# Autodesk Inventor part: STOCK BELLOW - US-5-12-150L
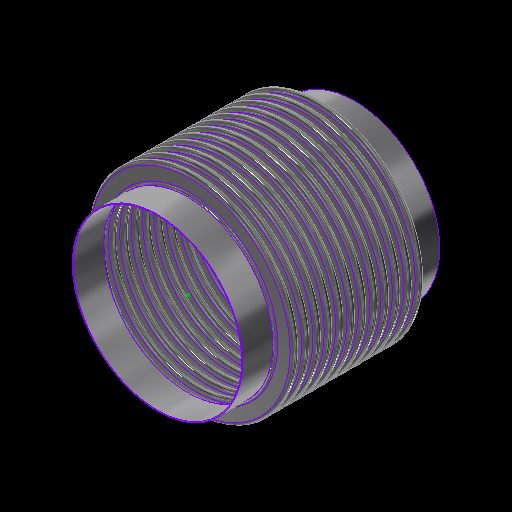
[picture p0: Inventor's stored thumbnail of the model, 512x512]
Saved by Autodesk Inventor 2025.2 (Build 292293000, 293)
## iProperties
Category: 22 GA (0.030 THICK)
RuleStatus: InUse
Created: 2024-01
Part Number: STOCK BELLOW - US-5-12-150L
Project: =STOCK BELLOWS: <Stock Number><SFILL>
Material: ASTM A240-304
Description: =STOCK BELLOWS: <Stock Number>, <SID_> I.D., <SOD_> O.D., <SPLY_> PLY, <Category>, <SNET_CONS> CONS.<PITCH_><STANGENT_> TANGENT<SFILL>
Document SubType Name: Sheet Metal
Designer: GS
Stock Number: U.S-5-12-150L
Surface Area: 4700.15 cm^2
Volume: 178.298 cm^3
Sheet Metal Rule: Default
Appearance: STAINLESS STEEL
Mass: 1436.6 g
Density: 8.05729 g/cm^3
THK: 0.036
ID: 3.500
OD: 4.250
CONS_: 2
PITCH: 0.500
TANGENT: 0.500
BELLOWS_UPSET: 0.000
d79: 1.000
d82: 1.000
d83: 26.000
d84: 24.000
d174: 8
d214: 8
STHK_: 0.030
SID_: 5.563
SOD_: 6.813
SPITCH_: 0.375
STANGENT__: 1.000
SBELLOWS_UPSET_: 0.000
SDIFF_TAN: 1.000
d252: 2
d275: 2
d287: 0.050
d289: 0.500
d290: 0.000
SOD_NECK: 5 5/8
PLY: 1
PSET: 4.178
PBAR: 1.035
COUNTER: 1.500
NET_TUBE: 3.071
CONS: 2
S_CONS: 0
NET_CONS: 2
ID_M: 88.90 mm
OD_M: 107.95 mm
THK_M: 0.91 mm
ID_U: 3.500 in
OD_U: 4.250 in
THK_U: 0.036 in
TANGENT2: 0.500
TAN_TO_TAN: 1.000 in
d80: 2.571
d81: 10
SID: 2.375
SCONS_: 12
SPITCH: 0.250
STANGENT_: 1.000
SBELLOWS_UPSET: 0.000
SNET_CONS: 12
SS_CONS: 0
SCONS: 8
d190: 8
d191: 1
d192: 1
d193: 8
d194: 0
SIZE: 5.00
PRESSURE: 150
d230: 8
STANGENT: 4.000
SPLY_: 1
d233: 8
d234: 0
d263: 2
d265: 1
d268: 2
d269: 0
d286: 2
d288: 1
d291: 2
d292: 0
SREROLL: 0.750
BLETP: 1.000 ul
PRES_Copy: 85
MATTABLE: 20 GA (0.036 THICK)
PART_NUMBER: U.S-5-12-150L
PITCH_: =, <SPITCH_> PITCH,
CFILL: .
SFILL: .
MESH: ,
COMP: 1.03
EXT: 0.52
LAT: 0.25
ANG: 573
ASR: 1021
LSR: 2605
ANSR: 77
PRES: 150
COMPM: 10.3
EXTM: 5.15
LATM: 2.50
ASRM: 178.808
PRESM: 10.342
LSRM: 456.214
ANSRM: 13.485
TEMPMIN: 20
TEMPMAX: 800
TEMPMINM: -7
TEMPMAXM: 427
WEIGHTM: 1.437
WEIGHT: 3.167
Author: GS
Keywords: 20 GA (0.036 THICK)
Comments: =STOCK BELLOW - <STOCK NUMBER>
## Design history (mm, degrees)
sketch "Sketch2"
  geometry: L1 (0, -177.245)-(0, 562.856) reference; L2 (45.364, 0)-(44.45, 0); L3 (48.082, -2.718)-(50.343, -2.718); L4 (48.082, -3.632)-(50.343, -3.632); L5 (50.343, -9.982)-(48.082, -9.982); L6 (50.343, -9.068)-(48.082, -9.068); L7 (45.364, -12.7)-(44.45, -12.7); L8 (48.082, 0)-(48.082, -12.7); L9 (50.343, -6.35)-(53.975, -6.35); L10 (44.45, 0)-(44.45, -12.7); L11 (20.376, 102.841)-(20.376, 101.926); L12 (58.262, 457.127)-(58.262, 349.177); L13 (58.262, 444.427)-(58.262, 336.477); L14 (93.133, -58.817)-(93.133, -71.517); L15 (118.746, -66.401)-(118.746, -66.401); L16 (50.343, -9.068)-(50.343, -9.982); L17 (48.082, -9.068)-(48.082, -9.982); L18 (48.082, -9.525)-(50.343, -9.525); L19 (53.975, 0)-(53.975, -12.7); L20 (-50.343, -9.068)-(-50.343, -9.982); L21 (-50.343, -2.718)-(-48.082, -2.718); L22 (-50.343, -3.632)-(-48.082, -3.632); L23 (-48.082, -9.068)-(-50.343, -9.068); L24 (-50.343, -9.525)-(-48.082, -9.525); L25 (-48.082, -9.982)-(-50.343, -9.982); L26 (-48.082, -9.068)-(-48.082, -9.982); L27 (-44.45, 0.653)-(-44.45, -12.047); L28 (-48.082, -6.35)-(-44.45, -6.35); L29 (-50.343, 0.653)-(-50.343, -12.7); L30 (-53.061, 0)-(-53.975, 0); L31 (-53.975, 0)-(-53.975, -12.7); L32 (-53.061, -12.7)-(-53.975, -12.7); A1 r 2.718 centre (48.082, 0) between (45.364, 0) and (48.082, -2.718); A2 r 3.632 centre (48.082, 0) between (44.45, 0) and (48.082, -3.632); A3 r 3.632 centre (50.343, -6.35) between (50.343, -9.982) and (50.343, -2.718); A4 r 2.718 centre (50.343, -6.35) between (50.343, -9.068) and (50.343, -3.632); A5 r 2.718 centre (48.082, -12.7) between (48.082, -9.982) and (45.364, -12.7); A6 r 3.632 centre (48.082, -12.7) between (48.082, -9.068) and (44.45, -12.7); A7 r 3.175 centre (50.343, -6.35) between (50.343, -9.525) and (53.518, -6.35); A8 r 3.175 centre (48.082, -12.7) between (48.082, -9.525) and (44.907, -12.7); A9 r 2.718 centre (-50.343, -12.7) between (-50.343, -9.982) and (-53.061, -12.7); A10 r 2.718 centre (-48.082, -6.35) between (-48.082, -9.068) and (-48.082, -3.632); A11 r 3.175 centre (-48.082, -6.35) between (-48.082, -9.525) and (-44.907, -6.35); A12 r 3.632 centre (-48.082, -6.35) between (-48.082, -9.982) and (-48.082, -2.718); A13 r 3.175 centre (-50.343, -12.7) between (-50.343, -9.525) and (-53.518, -12.7); A14 r 3.632 centre (-50.343, -12.7) between (-50.343, -9.068) and (-53.975, -12.7); A15 r 2.718 centre (-50.343, 0) between (-53.061, 0) and (-50.343, -2.718); A16 r 3.632 centre (-50.343, 0) between (-53.975, 0) and (-50.343, -3.632); 10 further points
  constraints: 62 end point, 38 point on circle, 20 tangent, 16 centre point, 12 parallel, 9 midpoint, 7 vertical, 6 coincident, 6 concentric, 6 point on line, 4 equal radius, 4 perpendicular, 3 horizontal, 1 collinear, 1 horizontal alignment, 10 other
  dimensions: "THK" = 0.9144 distance of L11.start L11.end; "ID" = 88.9 distance of L11.end point (20.376, 13.026); "OD" = 107.95 distance of L12.start L12.end; "PITCH" = 12.7 distance of L12.start L13.start; "TANGENT" = 12.7 distance of L14.start L14.end; "BELLOWS_UPSET" = 0 distance of L15.start L15.end; "d43" = 88.9 diameter of L10 L1 (= ID); "d44" = 107.95 diameter of L9.end L1 (= OD); "d45" = 0.9144 distance between parallel lines of L5 L6 (computed from THK, PLY); "d46" = 3.6322 radius of A3 (computed from PITCH, THK, PLY); "UPSET_PITCH" = 12.7 distance of L2.end L7.end (derived); "SIDEWALL_ANGLE" = 360 deg dimension on L3 L9 (derived); "CON_GAP" = 5.4356 distance of point (48.082, -9.068) point (48.082, -3.632) (derived); "TAN1" = 4.98728 dimension on A8 (derived); "TAN2" = 4.98728 dimension on A7 (derived); "LEG1" = 2.2606 distance of L18.start L18.end (derived); "d278" = 0.9144 distance between parallel lines of L25 L23 (derived); "d279" = 3.6322 radius of A12 (derived); "d280" = 12.7 distance of L30.end L31.end (derived); "d281" = 360 deg dimension on L21 L28 (derived); "d282" = 5.4356 distance of point (-50.343, -9.068) point (-50.343, -3.632) (derived); "d283" = 4.98728 dimension on A13 (derived); "d284" = 4.98728 dimension on A11 (derived); "d285" = 2.2606 distance of L24.start L24.end (derived); "d293" = 88.9 diameter of L27 L1 (derived); "d294" = 107.95 diameter of L31 L1 (derived)
  node "Sketch Rectangular Pattern1" dims "d31" = 25.4, "ID" = 88.9
  node "Sketch Rectangular Pattern2" dims "d39" = 25.4, "PITCH" = 12.7
revolve "CONS" stored, may be unused: angle "d48" = 90 deg
node "BELLOW MIDPLANE"
pattern_linear "Rectangular Pattern2" dims "d52" = 12.7 (= UPSET_PITCH)
sketch "Sketch5"
  geometry: C1 r 45.364 at (0, 0) reference; C2 r 44.45 at (0, 0) reference
extrude "TANGENT" new body sketch "Sketch5" distance "d53" = 12.7 (= TANGENT); taper "d54" = 0 deg
revolve "SAMETAN" stored, may be unused: angle "d65" = 90 deg
revolve "DIFFTAN" stored, may be unused: angle "d70" = 90 deg
sketch "Sketch9"
  geometry: L1 (53.319, 0)-(-53.319, 0) reference; L2 (0, -17.78)-(0, 17.78) reference; L3 (38.085, 0)-(-38.085, 0); L4 (38.085, -11.906)-(38.085, 11.906); L5 (25.385, -11.906)-(25.385, 11.906); L6 (13.15, 11.906)-(13.15, -11.906); L7 (-25.385, -11.906)-(-25.385, 11.906); L8 (-38.085, -11.906)-(-38.085, 11.906); L9 (37.291, -11.906)-(37.291, 11.906); L10 (38.085, -11.906)-(37.291, -11.906); L11 (38.085, 11.906)-(37.291, 11.906); L12 (13.546, 11.906)-(12.753, 11.906); L13 (12.753, 11.906)-(12.753, -11.906); L14 (12.753, -11.906)-(13.546, -11.906); L15 (13.546, -11.906)-(13.546, 11.906); L16 (-13.546, 11.906)-(-13.546, -11.906); L17 (-13.15, 11.906)-(-13.15, -11.906); L18 (-13.546, -11.906)-(-12.753, -11.906); L19 (-12.753, -11.906)-(-12.753, 11.906); L20 (-12.753, 11.906)-(-13.546, 11.906); L21 (-38.085, -11.906)-(-37.291, -11.906); L22 (-37.291, -11.906)-(-37.291, 11.906); L23 (-37.291, 11.906)-(-38.085, 11.906); L24 (-38.085, 11.906)-(-38.085, -11.906); L25 (38.085, -0.397)-(-38.085, -0.397); L26 (-38.085, -0.397)-(-38.085, 0.397); L27 (-38.085, 0.397)-(38.085, 0.397); L28 (38.085, 0.397)-(38.085, -0.397); L29 (-38.085, 11.906)-(38.085, 11.906); L30 (38.085, 11.906)-(38.085, 12.7); L31 (38.085, 12.7)-(-38.085, 12.7); L32 (-38.085, 12.7)-(-38.085, 11.906); L33 (38.085, -11.906)-(-38.085, -11.906); L34 (-38.085, -11.906)-(-38.085, -12.7); L35 (-38.085, -12.7)-(38.085, -12.7); L36 (38.085, -12.7)-(38.085, -11.906); 30 further points
  constraints: 68 end point, 13 midpoint, 13 parallel, 8 horizontal, 7 perpendicular, 6 equal length, 3 point on line, 2 vertical, 14 other
  dimensions: "d115" = 23.8125 distance of L4.start L4.end (derived); "d116" = 12.7 distance between parallel lines of L4 L5 (derived); "d117" = 12.23516 distance between parallel lines of L5 L6 (derived); "d125" = 38.53427 distance between parallel lines of L7 L6 (derived); "d127" = 12.7 distance between parallel lines of L8 L7 (derived); "d128" = 24.93516 distance between parallel lines of L6 L4 (derived); "d130" = 76.16943 distance between parallel lines of L8 L4 (derived); "RULER_THK" = 0.79375 distance between parallel lines of L4 L9; "d135" = 0.79375 distance of L13.end L14.end (derived); "d138" = 26.29911 distance of L13.end L16.end (derived); "d143" = 0.79375 distance of L22.end L8.end (derived); "d144" = 0.79375 distance between parallel lines of L27 L25 (derived)
extrude "RULER" join sketch "Sketch9" distance "d149" = 0.79375 (derived); taper "d150" = 0 deg
extrude "BARS" join sketch "Sketch9" distance "d151" = 0.79375 (derived); taper "d152" = 0 deg
pattern_linear "Rectangular Pattern4" dims "d155" = 26.29911 (derived)
sketch "Sketch13"
  geometry: L1 (93.149, -52.467)-(93.149, -77.867); L2 (71.412, 0)-(70.65, 0); L3 (71.412, -9.525)-(70.65, -9.525); L4 (83.763, -7.525)-(73.412, -7.525); L5 (83.763, -6.763)-(73.412, -6.763); L6 (83.763, -4.763)-(86.525, -4.763); L7 (73.412, -2)-(83.763, -2); L8 (73.412, 0)-(73.412, -9.525); L9 (70.65, 0)-(70.65, -9.525); L10 (58.254, -323.381)-(58.254, -496.431); L11 (58.254, -332.906)-(58.254, -505.956); L12 (58.254, -351.956)-(58.254, -525.006); L13 (58.254, -361.481)-(58.254, -534.531); L14 (58.254, -371.006)-(58.254, -544.056); L15 (58.254, -380.531)-(58.254, -553.581); L16 (58.254, -390.056)-(58.254, -563.106); L17 (58.254, -342.431)-(58.254, -515.481); L18 (20.376, 102.688)-(20.376, 101.926); L19 (73.412, -2.762)-(83.763, -2.762); L20 (0, -696.265)-(0, 235.847) reference; L21 (-23.752, 0)-(142.514, 0) reference; A1 r 2 centre (73.412, 0) between (71.412, 0) and (73.412, -2); A2 r 2 centre (73.412, -9.525) between (73.412, -7.525) and (71.412, -9.525); A3 r 2.762 centre (73.412, -9.525) between (73.412, -6.763) and (70.65, -9.525); A4 r 2 centre (83.763, -4.763) between (83.763, -6.763) and (83.763, -2.762); A5 r 2.762 centre (83.763, -4.763) between (83.763, -7.525) and (83.763, -2); A6 r 2.762 centre (73.412, 0) between (70.65, 0) and (73.412, -2.762); 6 further points; 1 other entity
  constraints: 38 end point, 15 point on circle, 9 tangent, 6 centre point, 6 parallel, 5 vertical alignment, 4 point on line, 4 vertical, 3 coincident, 3 concentric, 2 collinear, 2 equal radius, 1 horizontal, 1 perpendicular, 23 other
  dimensions: "SBELLOWS_UPSET_" = 0 distance of point (118.762, -66.401) point (118.762, -66.401); "STOTAL_THK_BELLOW__" = 0.762 distance between parallel lines of L4 L5 (derived); "d224" = 2.76225 radius of A5 (derived); "d225" = 9.525 distance of L2.end L3.end (derived); "SSIDEWALL_ANGLE_" = 360 deg dimension on L7 L6 (derived); "SSCON_GAP_" = 4.0005 distance of point (73.412, -6.763) point (73.412, -2.762) (derived); "d235" = 141.3002 diameter of L9 L20 (derived); "d236" = 173.0502 diameter of L6.end L20 (derived)
  node "Sketch Rectangular Pattern4" dims "d228" = 25.4
  node "Sketch Rectangular Pattern5" dims "d229" = 25.4
revolve "SBELLOW" stored, may be unused: angle "d197" = 90 deg
pattern_linear "Rectangular Pattern5" dims "d204" = 9.525 (derived)
revolve "STANGENT" stored, may be unused: angle "d240" = 90 deg
revolve "SSAMETAN" stored, may be unused: angle "d241" = 90 deg
revolve "SDIFFTAN" stored, may be unused: angle "d246" = 90 deg
revolve "INVCON" stored, may be unused: angle "d295" = 90 deg
pattern_linear "Rectangular Pattern6" dims "d298" = 12.7 (derived)
revolve "INVTANGENT" stored, may be unused: angle "d302" = 90 deg
revolve "INVSAMETAN" stored, may be unused: angle "d307" = 90 deg
revolve "INVDIFFTAN" stored, may be unused: angle "d312" = 90 deg
sketch "ID BELLOW MOUNT CALC"
  geometry: L1 (44.45, 0)-(38.1, 0); L2 (38.1, 0)-(38.1, 12.7); L3 (38.1, 12.7)-(44.45, 12.7); L4 (44.45, 12.7)-(44.45, 0); L5 (36.513, 12.7)-(35.598, 12.7); L6 (35.598, 12.7)-(35.598, 0); L7 (35.598, 0)-(36.513, 0); L8 (36.513, 0)-(36.513, 12.7); L9 (0, -2.54)-(0, 15.24) reference; L10 (-8.89, 0)-(53.34, 0) reference; 1 further point
  constraints: 16 end point, 5 parallel, 2 collinear, 2 horizontal, 2 perpendicular
  dimensions: "d314" = 12.7 distance of L5.end L6.end (derived); "d315" = 0.9144 distance of L5.start L5.end (derived); "IG" = 1.5875 distance between parallel lines of L2 L8; "PIPE_OD" = 88.9 diameter of L4 L9; "PIPE_WALL" = 6.35 distance of L2.end L3.end; "ID_MT_BELLOW" = 71.1962 diameter of L6 L9 (derived)
revolve "CFILL" stored, may be unused: angle "d320" = 90 deg
pattern_linear "Rectangular Pattern7" dims "d323" = 12.7 (derived)
revolve "SFILL" stored, may be unused: angle "d324" = 90 deg
pattern_linear "Rectangular Pattern8" dims "d327" = 9.525 (derived)
node "STOCK BELLOW MIDPLANE"
node "BELLOW"
sketch "Sketch6"
  geometry: L1 (-12.7, 45.364)-(0, 45.364); L2 (0, 45.364)-(0, 44.45); L3 (0, 44.45)-(-12.7, 44.45); L4 (-12.7, 44.45)-(-12.7, 45.364); L5 (10.16, 0)-(-60.96, 0) reference; L6 (-38.1, -89.422)-(-38.1, 153.44) reference; 1 further point
  constraints: 8 end point, 2 parallel, 1 horizontal, 1 perpendicular
  dimensions: "d61" = 12.7 distance of L2.end L3.end (derived); "d62" = 0.9144 distance of L1.end L2.end (derived); "d63" = 88.9 diameter of L3 L5 (derived); "d64" = 25.4 distance between parallel lines of L4 L6 (derived)
sketch "Sketch12"
  geometry: 1 further point
sketch "Sketch14"
  geometry: L1 (-25.4, 71.412)-(0, 71.412); L2 (0, 71.412)-(0, 70.65); L3 (0, 70.65)-(-25.4, 70.65); L4 (-25.4, 70.65)-(-25.4, 71.412); L5 (5.08, 0)-(-30.48, 0) reference; L6 (0, -14.282)-(0, 85.695) reference; 1 further point
  constraints: 8 end point, 2 parallel, 1 collinear, 1 horizontal, 1 perpendicular
  dimensions: "d237" = 0.762 distance of L3.end L1.start (derived); "d238" = 141.3002 diameter of L3 L5 (derived); "d239" = 25.4 distance of L1.start L1.end (derived); "SOD_NECK" = 142.8242 diameter of L1 L5 (derived)
sketch "Sketch15"
  geometry: L1 (-14.282, 0)-(85.695, 0) reference; L2 (70.65, -114.3)-(71.412, -114.3); L3 (71.412, -114.3)-(71.412, -139.7); L4 (71.412, -139.7)-(70.65, -139.7); L5 (70.65, -139.7)-(70.65, -114.3); L6 (0, -170.18)-(0, 43.18) reference; 1 further point
  constraints: 8 end point, 2 parallel, 1 horizontal, 1 perpendicular
  dimensions: "d205" = 25.4 distance of L4.end L2.start (derived); "d206" = 0.762 distance of L3.end L4.end (derived); "d207" = 141.3002 diameter of L5 L6 (derived); "d208" = 114.3 distance between parallel lines of L1 L2 (derived)
node "TANGENT_"
node "SAME_TAN"
sketch "Sketch8"
  geometry: L1 (45.364, -25.4)-(44.45, -25.4); L2 (44.45, -25.4)-(44.45, -38.1); L3 (44.45, -38.1)-(45.364, -38.1); L4 (45.364, -38.1)-(45.364, -25.4); L5 (0, -48.26)-(0, 22.86) reference; L6 (-89.422, 0)-(153.44, 0) reference; 1 further point
  constraints: 8 end point, 2 parallel, 1 horizontal, 1 perpendicular
  dimensions: "d66" = 88.9 diameter of L2 L5 (derived); "TOTAL_THK_BELLOW" = 0.9144 distance of L2.end L3.end (derived); "d68" = 25.4 distance between parallel lines of L1 L6 (derived); "d69" = 12.7 distance of L1.end L2.end (derived)
node "DIFF_TAN"
node "Sketch Rectangular Pattern3" dims "d138" = 26.29911 (derived), "d141" = 25.4
node "SBELLOW_"
node "STANGENT_"
node "SSAME_TAN"
sketch "Sketch16"
  geometry: L1 (71.412, -114.3)-(70.65, -114.3); L2 (70.65, -114.3)-(70.65, -139.7); L3 (70.65, -139.7)-(71.412, -139.7); L4 (71.412, -139.7)-(71.412, -114.3); L5 (0, -170.18)-(0, 43.18) reference; L6 (-14.282, 0)-(85.695, 0) reference; 1 further point
  constraints: 8 end point, 2 parallel, 1 horizontal, 1 perpendicular
  dimensions: "SDIFF_TAN" = 25.4 distance of L3.end L1.start; "d243" = 0.762 distance of L2.end L3.end (derived); "d244" = 114.3 distance between parallel lines of L1 L6 (derived); "d245" = 141.3002 diameter of L2 L5 (derived)
node "SDIFF_TAN"
body "Solid15"
sketch "Sketch17"
  geometry: L1 (53.975, 12.7)-(53.061, 12.7); L2 (53.061, 12.7)-(53.061, 0); L3 (53.061, 0)-(53.975, 0); L4 (53.975, 0)-(53.975, 12.7); L5 (0, -2.54)-(0, 15.24) reference; L6 (-10.795, 0)-(64.77, 0) reference; 2 further points
  constraints: 8 end point, 2 parallel, 1 horizontal, 1 midpoint, 1 perpendicular, 1 point on line
  dimensions: "INVTANGENT" = 12.7 distance of L3.end L1.start (derived); "d300" = 0.9144 distance of L1.start L1.end (derived); "d301" = 107.95 diameter of L4 L5 (derived)
body "Solid16"
sketch "Sketch18"
  geometry: L1 (53.975, -25.4)-(53.061, -25.4); L2 (53.061, -25.4)-(53.061, -38.1); L3 (53.061, -38.1)-(53.975, -38.1); L4 (53.975, -38.1)-(53.975, -25.4); L5 (-10.795, 0)-(64.77, 0) reference; L6 (0, -48.26)-(0, 22.86) reference; 1 further point
  constraints: 8 end point, 2 parallel, 1 horizontal, 1 perpendicular
  dimensions: "d303" = 25.4 distance between parallel lines of L1 L5 (derived); "d304" = 12.7 distance of L3.end L1.start (derived); "d305" = 0.9144 distance of L2.end L3.end (derived); "d306" = 107.95 diameter of L4 L6 (derived)
body "Solid17"
sketch "Sketch19"
  geometry: L1 (53.975, -25.4)-(53.061, -25.4); L2 (53.061, -25.4)-(53.061, -38.1); L3 (53.061, -38.1)-(53.975, -38.1); L4 (53.975, -38.1)-(53.975, -25.4); L5 (0, -48.26)-(0, 22.86) reference; L6 (-10.795, 0)-(64.77, 0) reference; 1 further point
  constraints: 8 end point, 2 parallel, 1 horizontal, 1 perpendicular
  dimensions: "d308" = 12.7 distance of L1.end L2.end (derived); "d309" = 107.95 diameter of L4 L5 (derived); "d310" = 0.9144 distance of L2.end L3.end (derived); "d311" = 25.4 distance between parallel lines of L1 L6 (derived)
body "Solid18"
body "Solid19"
body "Solid20"
other parameters: "BMPL" = -57.15, "PSET" = 106.1212 (computed from OD, THK, PLY) [user parameter], "PBAR" = 26.29911 (= 0.570796 x PITCH + OD - ID) [user parameter; used in 1 equation term], "COUNTER" = 15 [user parameter], "NET_TUBE" = 77.99823 (computed from CONS_, PBAR, TANGENT) [user parameter], "S_CONS" = 0 [user parameter; used in 1 equation term], "ID_M" = 88.9 (= ID) [user parameter], "OD_M" = 107.95 (= OD) [user parameter], "THK_M" = 0.9144 (= THK) [user parameter], "ID_U" = 88.9 (= ID) [user parameter], "OD_U" = 107.95 (= OD) [user parameter], "THK_U" = 0.9144 (= THK) [user parameter], "D_UNITS" = 0 [user parameter], "TANGENT2" = 12.7 [user parameter], "TAN_TO_TAN" = 25.4 [user parameter], "OD_NECK" = 90.7288 [user parameter], "d79" = 25.4, "d80" = 65.29823 [user parameter], "d82" = 25.4, "d83" = 660.4, "d84" = 609.6, "sa_0" = 4, "FRAME_THK" = 0.79375 [user parameter], "CON_FLAT" = 12.23516 [user parameter], "SID" = 60.325 [user parameter], "SPITCH" = 6.35 [user parameter], "STANGENT_" = 25.4 [user parameter], "SBELLOWS_UPSET" = 0 [user parameter], "SS_CONS" = 0 [user parameter], "STAN_TO_TAN_" = 114.3 [user parameter], "d100" = 0.762 [user parameter], "d191" = 25.4 [user parameter], "d194" = 0 [user parameter], "STANGENT" = 101.6 [user parameter], "d234" = 0 [user parameter], "SUPSET_PITCH_" = 9.525 [user parameter], "d269" = 0 [user parameter], "d287" = 1.27, "d289" = 12.7, "d290" = 0, "d292" = 0 [user parameter], "Thickness" = 3.048 (derived), "KFactor" = 4.4, "BendRadius" = 3.048 (derived), "BendReliefWidth" = 3.048 (derived), "BendReliefDepth" = 1.524 (derived), "CornerReliefSize" = 12.192 (derived), "SeamGap" = 0.00508, "MinimumRemnant" = 6.096 (derived), "TransitionRadius" = 3.048 (derived), "JacobiRadiusSize" = 3.048 (derived), "GapSize" = 3.048 (derived), "SREROLL" = 19.05 [user parameter], "CUR_STK_PITCH" = 9.525 [user parameter], "d328" = -57.15 (derived), "ASR" = 10210 [user parameter], "LSR" = 26050 [user parameter], "BLETP" = 1 [user parameter], "ASRM" = 1788.0773 [user parameter], "PRESM" = 103.41975 [user parameter], "LSRM" = 4562.1365 [user parameter], "ANSRM" = 134.8501 [user parameter], "TEMPMIN" = 2664.83333 [user parameter], "TEMPMAX" = 6998.16667 [user parameter], "TEMPMINM" = 2664.83333 [user parameter], "TEMPMAXM" = 6998.16667 [user parameter], "WEIGHT" = 14.36602 [user parameter], "WEIGHTM" = 0.01437 [user parameter]
